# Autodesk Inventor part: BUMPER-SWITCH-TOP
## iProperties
Created: 2007-08
Part Number: BUMPER-SWITCH-TOP
Material: ABS Plastic
Document SubType Name: Modeling
Density: 1.06 g/cm^3
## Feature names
1. Base1
